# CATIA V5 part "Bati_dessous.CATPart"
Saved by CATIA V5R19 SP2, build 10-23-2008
Part number: Bati
Bounding box of the stored display mesh (mm): x 0 to 250, y -125 to 125, z -25 to 0
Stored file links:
  C:\Users\Romain\Documents\IFMA\2A\cours\S3\Projet CFAO-IAO\IAO\Catia\Bati\Bati_dessous.CATPart
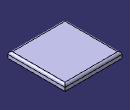
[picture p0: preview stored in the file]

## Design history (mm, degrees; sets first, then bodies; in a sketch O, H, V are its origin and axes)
Body1 (main body)
  Sketch1 on yz-plane, origin (0, 0, 0), H (0, 1, 0), V (0, 0, 1)
    point P1 (-125, 0)
    line L1 (-125, 0) -> (125, 0)
    line L2 (125, 0) -> (125, -25)
    line L3 (125, -25) -> (-125, -25)
    line L4 (-125, -25) -> (-125, 0)
    length L1 = 250
    distance O L4 = 125
    length L2 = 25
    coincidence: P1 H
    horizontal: L1 H, L3 H
    vertical: L2 V, L4 V
  Pad1: profile Sketch1, direction (1, 0, 0), length 250
  Fillet1: radius 10, on face of Pad1 from Sketch1.L1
